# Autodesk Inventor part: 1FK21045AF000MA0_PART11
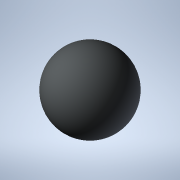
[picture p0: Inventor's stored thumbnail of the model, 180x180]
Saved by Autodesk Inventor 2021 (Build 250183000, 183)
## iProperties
Created: 2025-04
Part Number: 1FK21045AF000MA0_PART11
Material: Generic
Catalog Web Link: www.3dfindit.com
Description: -Servo synchronous motor
Document SubType Name: Modeling
Designer: psAdmin
Mass: 0.137258 g
Surface Area: 1.2868 cm^2
Volume: 0.137258 cm^3
Density: 1 g/cm^3
Appearance: PSOLRGB-212-217-219
Category: PARTsolutions
Title: 1FK21045AF000MA0_PART11
Author: Cadenas PARTsolutions
Comments: Servo synchronous motor
Sending System: PARTsolutions
Preprocessor: ST-DEVELOPER v19.3
PSOL_IDENT_0: {$CADENAS_DATA/23d-libs/siemens_ag/_cat_/8b/0a/1fk21045af000ma0.prj},216 {VTYP=3D},{NB=1FK21045AF000
PSOL_IDENT_1: MA0_PART11},{LINA=1FK21045AF000MA0_PART11},{NN=1FK21045AF000MA0_PART11},{NOPRJ=TRUE},{DATE=19.08.202
PSOL_IDENT_2: 5 14:00:48},{GEOMDATE=30.07.2025 02:00:28},{VERSION=},{LINEID=10},{WBVAR=},{WBNUMERIC=}  {NB=1FK2104
PSOL_IDENT_3: 5AF000MA0_PART11},{LINA=1FK21045AF000MA0_PART11},{KT=DUMMY},{PREVIEW=../../../_pool_/a9/69/p_d211_xx
PSOL_IDENT_4: _00818j.png},{DESCSHORT=SIMOTICS S-1FK2 HD, SINAMICS S210 3AC 400V-480V, 2.4 Nm, 3000 rpm},{DESCLONG=
PSOL_IDENT_5: SIMOTICS S-1FK2 HD servo motor M0=2.4 Nm; PN = 0.75 kW at nN=3000 rpm (380-480 V); PN = 0.375 kW at
PSOL_IDENT_6: nN=1500 rpm (200-240 V); degree of protection IP64; cylindrical shaft D19x40mm; absolute encoder 22-
PSOL_IDENT_7: bit + 12-bit multiturn (encoder AM22DQC); with OCC interface; plug size M17, rotatable; SIMOTICS S-1
PSOL_IDENT_8: FK2 servomotorfor a wide range of uses in industrial environments. SIMOTICS S‑1FK2 servomotors are c
PSOL_IDENT_9: ompact synchronous motors with a high dynamic performance that set themselves apart as a result of t
PSOL_IDENT_10: heir high power density, degree of protection and overload capability. The motors are available in t
PSOL_IDENT_11: wo variants: as High Dynamic variant (highest dynamic performance as a result of the low intrinsic m
PSOL_IDENT_12: oment of inertia for applications demanding a high dynamic performance with low moved masses) - and
PSOL_IDENT_13: as Compact variant (precise and stable closed-loop control for medium up to large moved masses as a
PSOL_IDENT_14: result of a medium intrinsic moment of inertia). SIMOTICSS‑1FK2 servomotors fully exploit their stre
PSOL_IDENT_15: ngths in a system with the SINAMICSS210 frequency converter and simple connection using the one cabl
PSOL_IDENT_16: e connection (OCC). Advantages include the short control and positioning times, fast and precise cor
PSOL_IDENT_17: rection of disturbing quantities as well as stable control with a high dynamic performance. The serv
PSOL_IDENT_18: o motors can be configured to address a wide range of requirements. For example with and without hol
PSOL_IDENT_19: ding brake, IP64 or IP65 degree of protection, singleturn or multiturn absolute encoders - to name j
PSOL_IDENT_20: ust a few. Further, the servomotors are available in different shaft heights extending from 20 to 10
PSOL_IDENT_21: 0. A shaft sealing ring is available to achieve an IP65 degree of protection and for subsequent moun
PSOL_IDENT_22: ting at the motor or as spare part. SIMOTICS - the optimum motor for each and every motion control a
PSOL_IDENT_23: pplication.},{INTNO=195125050112},{SUPPLIERALTNO=1FK2104-5AF00-0MA0},{MANUID=1FK21045AF000MA0},{MANU
PSOL_IDENT_24: NAME=Siemens},{MANUTYPEDESC=Synchronous motor 1FK2-HD 2.4 NM},{AAU732=SIMOTICS},{AAO057=S-1FK2},{AAU
PSOL_IDENT_25: 734=SIMOTICS S-1FK2 HD servo motor M0=2.4 Nm; PN = 0.75 kW at nN=3000 rpm (380-480 V); PN = 0.375 kW
PSOL_IDENT_26: at nN=1500 rpm (200-240 V); degree of protection IP64; cylindrical shaft D19x40mm; absolute encoder
PSOL_IDENT_27: 22-bit + 12-bit multiturn (encoder AM22DQC); with OCC interface; plug size M17, rotatable;},{AAW338=
PSOL_IDENT_28: Synchronous motor 1FK2-HD 2.4 NM},{AAO742=SIMOTICS},{AAO663=4042948692912},{NOCUPEROU=1},{PRICEQUANT
PSOL_IDENT_29: ITY=1},{QUANTITYMIN=1},{QUANTITYINT=1},{CTN=85015100},{COO=DE},{AAO676=1FK2104-5AF00-0MA0},{AAO677=S
PSOL_IDENT_30: iemens AG},{ORDERUNIT=C62},{CONTENTUNIT=C62}
NB: 1FK21045AF000MA0_PART11
NT: Servo synchronous motor
NBSYN: $MANUID._PART11
LINA: 1FK21045AF000MA0_PART11
CATALOG: SIEMENS
PREVIEW: ../../../_pool_/a9/69/p_d211_xx_00818j.png
DESCSHORT: SIMOTICS S-1FK2 HD, SINAMICS S210 3AC 400V-480V, 2.4 Nm, 3000 rpm
DESCLONG: SIMOTICS S-1FK2 HD servo motor M0=2.4 Nm; PN = 0.75 kW at nN=3000 rpm (380-480 V); PN = 0.375 kW at nN=1500 rpm (200-240 V); degree of protection IP64; cylindri
INTNO: 195125050112
SUPPLIERALTNO: 1FK2104-5AF00-0MA0
MANUID: 1FK21045AF000MA0
MANUNAME: Siemens
MANUTYPEDESC: Synchronous motor 1FK2-HD 2.4 NM
AAU732: SIMOTICS
AAO057: S-1FK2
AAU734: SIMOTICS S-1FK2 HD servo motor M0=2.4 Nm; PN = 0.75 kW at nN=3000 rpm (380-480 V); PN = 0.375 kW at nN=1500 rpm (200-240 V); degree of protection IP64; cylindri
AAW338: Synchronous motor 1FK2-HD 2.4 NM
AAO742: SIMOTICS
AAO663: 4042948692912.0
NOCUPEROU: 1
PRICEQUANTITY: 1
QUANTITYMIN: 1
QUANTITYINT: 1
CTN: 85015100
COO: DE
ARTICLENO: 1FK21045AF000MA0_PART11
BOMINFO: 1FK21045AF000MA0_PART11
CREATOR: CADENAS GmbH
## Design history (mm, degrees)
feature "2025_04_17_15_40_42_0766"
body "Solid1"
